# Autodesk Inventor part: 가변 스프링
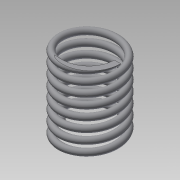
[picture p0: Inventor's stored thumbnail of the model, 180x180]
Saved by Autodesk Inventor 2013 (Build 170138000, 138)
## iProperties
Created: 2015-01
Part Number: 가변 스프링
Material: 일반
Document SubType Name: Modeling
Designer: hanacad7
Density: 1 g/cm^3
Author: hanacad7
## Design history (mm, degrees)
sketch "스케치1"
  geometry: L1 (0, 0)-(17.5, 0); L2 (17.5, 0)-(17.5, 48.5); L3 (17.5, 48.5)-(0, 48.5); L4 (0, 48.5)-(0, 0); C1 r 2 at (17.5, 0)
  constraints: 8 end point, 2 parallel, 1 centre point, 1 coincident, 1 horizontal, 1 perpendicular
  dimensions: "d0" = 4 diameter of C1; "d2" = 35 diameter of L2 L4; "d3" = 48.5 distance between parallel lines of L1 L3 (derived)
feature "코일1" sketch "스케치1" pitch "d4" = 10; turns "d6" = 7.5; dims "d5" = 48.5 (= d3), "d7" = 0, angle "d8" = 90 deg, angle "d9" = 90 deg, "d10" = 0, "d11" = 0
sketch "스케치2"
  geometry: L1 (-19.5, 0)-(-15.5, 0) reference; 1 further point
  constraints: 1 horizontal alignment
extrude "돌출1" cut sketch "스케치2" stored distance "d12" = 10; taper "d13" = 0 deg
node "작업 평면1"
sketch "스케치3"
  geometry: L1 (15.5, 0)-(19.5, 0) reference; 1 further point
  constraints: 1 horizontal alignment
extrude "돌출2" cut sketch "스케치3" stored distance "d14" = 10; taper "d15" = 0 deg
node "솔리드1"
node "절단 모서리 투영1"
node "절단 모서리 투영2"
